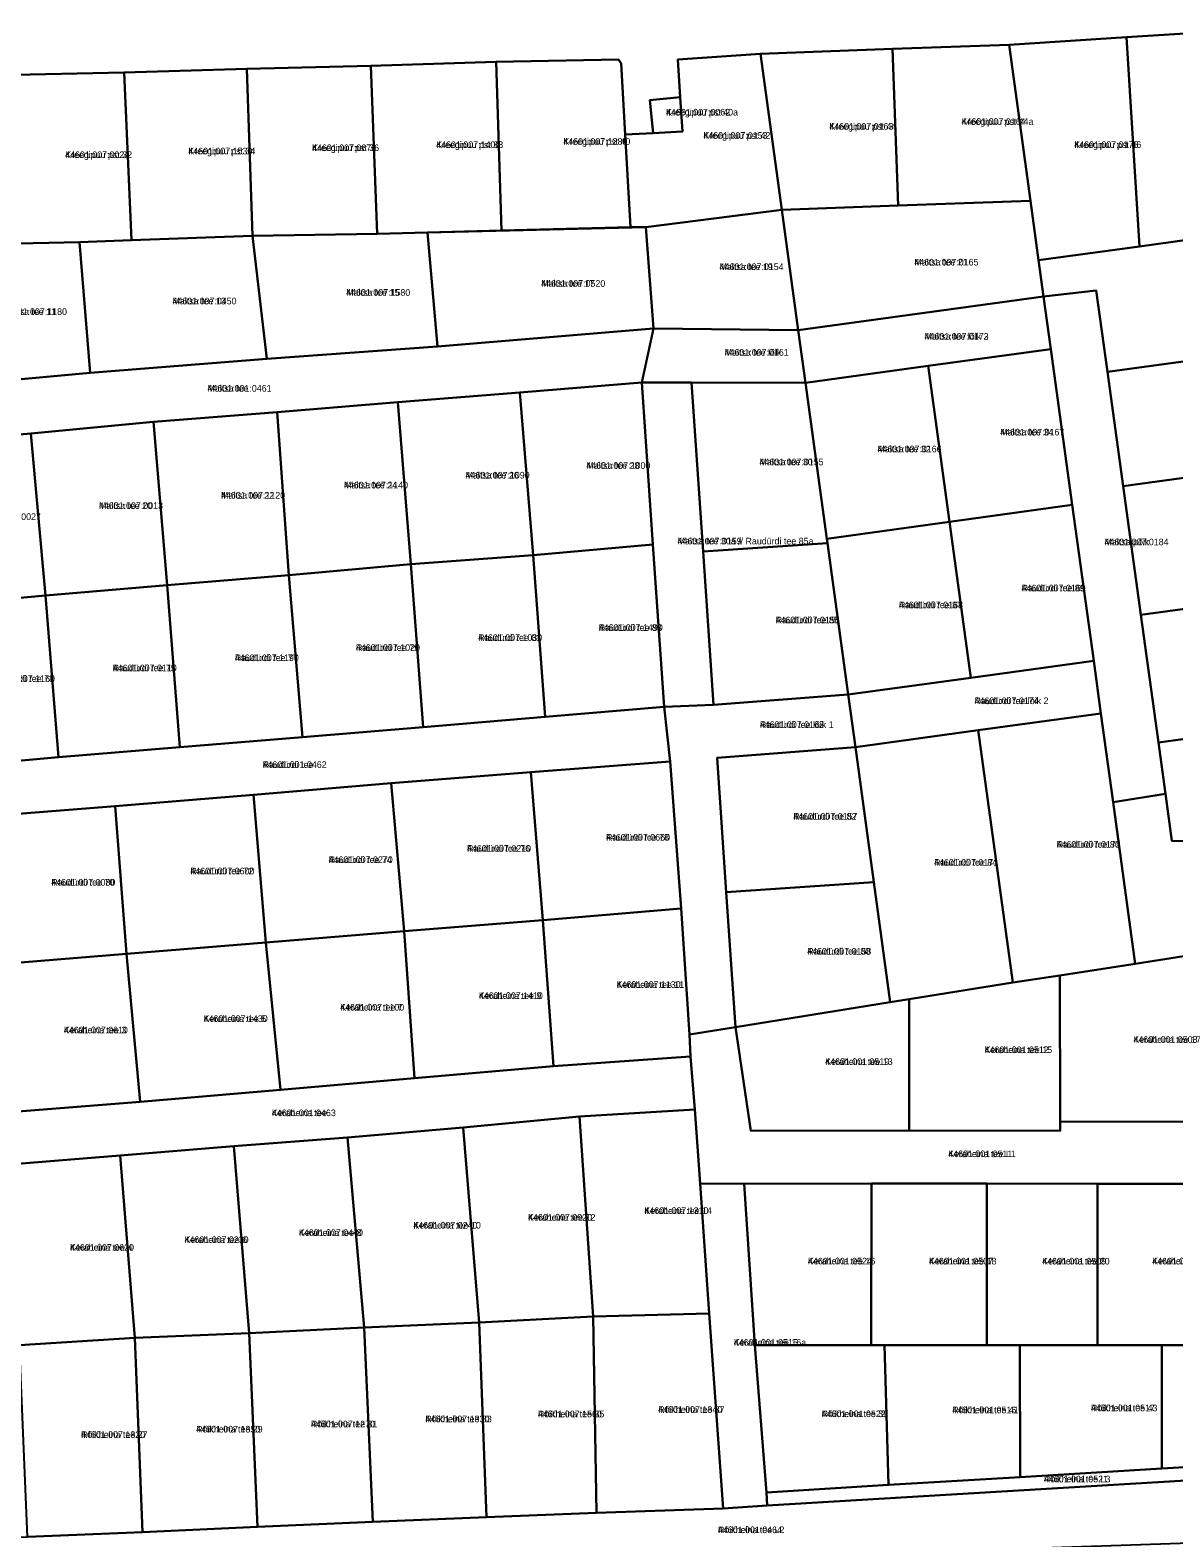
# Model space of a CAD drawing. Extents: x 551843 to 558501, y 6589003 to 6595718.
# Drawn here: x 554119.5 to 554378.5, y 6592709.8 to 6593051.3 of the extents above; entities that cross this region are included whole.
import ezdxf

# ---------------------------------------------------------------- set-up
doc = ezdxf.new("R2010")
doc.units = 0
for name, color, linetype in [('L_AADRESS', 7, 'Continuous'), ('PIIR', 7, 'Continuous'), ('TUNNUS', 7, 'Continuous')]:
    doc.layers.add(name, color=color, linetype=linetype)

msp = doc.modelspace()

# ---------------------------------------------------------------- linework, layer by layer
at = {"layer": 'PIIR'}
msp.add_lwpolyline([(554393.23, 6593051.33), (554367.77, 6593049.72), (554341.21, 6593048.04), (554314.82, 6593047.08), (554284.88, 6593045.98), (554266.15, 6593044.67), (554266.74, 6593036.15), (554259.82, 6593035.44), (554260.58, 6593028.02), (554254.24, 6593027.69), (554253.32, 6593043.75), (554252.74, 6593044.67), (554225.05, 6593044.16), (554196.68, 6593043.29), (554168.59, 6593042.59), (554140.76, 6593041.72), (554112.35, 6593041.16), (554083.78, 6593040.41), (554051.46, 6593039.45), (554047.89, 6593060.25)], dxfattribs=at)
for points in [[(554367.77, 6593049.72), (554393.23, 6593051.33), (554395.81, 6593015.41), (554397.21, 6593005.99), (554370.76, 6593002.33)], [(554314.82, 6593047.08), (554341.21, 6593048.04), (554346.06, 6593012.7), (554316.12, 6593011.6)], [(554341.21, 6593048.04), (554367.77, 6593049.72), (554370.76, 6593002.33), (554347.91, 6592999.22), (554346.06, 6593012.7)], [(554252.74, 6593044.67), (554253.32, 6593043.75), (554254.24, 6593027.69), (554255.46, 6593006.67), (554226.23, 6593005.95), (554225.05, 6593044.16)], [(554266.15, 6593044.67), (554284.88, 6593045.98), (554289.73, 6593010.63), (554258.95, 6593006.73), (554255.46, 6593006.67), (554254.24, 6593027.69), (554260.58, 6593028.02), (554267.22, 6593028.37), (554266.74, 6593036.15)], [(554284.88, 6593045.98), (554314.82, 6593047.08), (554316.12, 6593011.6), (554289.73, 6593010.63)], [(554130.68, 6593003.34), (554113.25, 6593002.9), (554112.35, 6593041.16), (554140.76, 6593041.72), (554142.47, 6593003.75)], [(554140.76, 6593041.72), (554168.59, 6593042.59), (554169.86, 6593004.71), (554142.47, 6593003.75)], [(554196.68, 6593043.29), (554198.09, 6593005.16), (554169.86, 6593004.71), (554168.59, 6593042.59)], [(554198.09, 6593005.16), (554196.68, 6593043.29), (554225.05, 6593044.16), (554226.23, 6593005.95), (554209.46, 6593005.46)], [(554266.74, 6593036.15), (554267.22, 6593028.37), (554260.58, 6593028.02), (554259.82, 6593035.44)], [(554258.95, 6593006.73), (554289.73, 6593010.63), (554293.47, 6592983.34), (554260.66, 6592983.71)], [(554289.73, 6593010.63), (554316.12, 6593011.6), (554346.06, 6593012.7), (554347.91, 6592999.22), (554349.04, 6592990.97), (554293.47, 6592983.34)], [(554142.47, 6593003.75), (554169.86, 6593004.71), (554173.07, 6592976.86), (554133.06, 6592973.7), (554130.68, 6593003.34)], [(554169.86, 6593004.71), (554198.09, 6593005.16), (554209.46, 6593005.46), (554211.72, 6592979.66), (554173.07, 6592976.86)], [(554209.46, 6593005.46), (554258.95, 6593006.73), (554260.66, 6592983.71), (554211.72, 6592979.66)], [(554347.91, 6592999.22), (554370.76, 6593002.33), (554397.21, 6593005.99), (554400.85, 6592981.48), (554401.21, 6592979.08), (554363.49, 6592973.9), (554360.96, 6592992.34), (554349.04, 6592990.97)], [(554093.35, 6593002.34), (554113.25, 6593002.9), (554130.68, 6593003.34), (554133.06, 6592973.7), (554095.98, 6592970.3)], [(554293.47, 6592983.34), (554349.04, 6592990.97), (554350.68, 6592979.08), (554322.88, 6592975.26), (554295.1, 6592971.45)], [(554349.04, 6592990.97), (554360.96, 6592992.34), (554363.49, 6592973.9), (554367.05, 6592947.99), (554371.05, 6592918.84), (554375.02, 6592889.95), (554376.62, 6592878.3), (554364.77, 6592876.42), (554362.01, 6592896.54), (554360.38, 6592908.43), (554355.53, 6592943.76), (554350.68, 6592979.08)], [(554061.41, 6592967.05), (554095.98, 6592970.3), (554133.06, 6592973.7), (554173.07, 6592976.86), (554211.72, 6592979.66), (554260.66, 6592983.71), (554258, 6592971.5), (554230.39, 6592969.26), (554202.78, 6592967.02), (554175.41, 6592964.8), (554147.41, 6592962.61), (554119.61, 6592959.98), (554091.85, 6592957.57), (554062.46, 6592955.16)], [(554260.66, 6592983.71), (554293.47, 6592983.34), (554295.1, 6592971.45), (554269.29, 6592971.48), (554258, 6592971.5)], [(554322.88, 6592975.26), (554350.68, 6592979.08), (554355.53, 6592943.76), (554327.73, 6592939.94)], [(554363.49, 6592973.9), (554401.21, 6592979.08), (554405.05, 6592953.2), (554367.05, 6592947.99)], [(554295.1, 6592971.45), (554322.88, 6592975.26), (554327.73, 6592939.94), (554299.94, 6592936.12)], [(554260.5, 6592934.8), (554233.44, 6592932.37), (554230.39, 6592969.26), (554258, 6592971.5)], [(554258, 6592971.5), (554269.29, 6592971.48), (554271.9, 6592933.21), (554274.26, 6592898.5), (554263.08, 6592898.06), (554260.5, 6592934.8)], [(554269.29, 6592971.48), (554295.1, 6592971.45), (554299.94, 6592936.12), (554300.08, 6592935.13), (554271.9, 6592933.21)], [(554205.74, 6592930.34), (554178.05, 6592927.87), (554175.41, 6592964.8), (554202.78, 6592967.02)], [(554233.44, 6592932.37), (554205.74, 6592930.34), (554202.78, 6592967.02), (554230.39, 6592969.26)], [(554122.96, 6592923.26), (554119.61, 6592959.98), (554147.41, 6592962.61), (554150.53, 6592925.62)], [(554147.41, 6592962.61), (554175.41, 6592964.8), (554178.05, 6592927.87), (554150.53, 6592925.62)], [(554119.61, 6592959.98), (554122.96, 6592923.26), (554095.24, 6592920.69), (554091.85, 6592957.57)], [(554367.05, 6592947.99), (554405.05, 6592953.2), (554407.03, 6592939.78), (554409.37, 6592924.1), (554371.05, 6592918.84)], [(554327.73, 6592939.94), (554355.53, 6592943.76), (554360.38, 6592908.43), (554332.58, 6592904.61)], [(554299.94, 6592936.12), (554327.73, 6592939.94), (554332.58, 6592904.61), (554304.78, 6592900.8), (554300.08, 6592935.13)], [(554271.9, 6592933.21), (554300.08, 6592935.13), (554304.78, 6592900.8), (554274.26, 6592898.5)], [(554233.44, 6592932.37), (554236.15, 6592895.73), (554208.49, 6592893.43), (554205.74, 6592930.34)], [(554233.44, 6592932.37), (554260.5, 6592934.8), (554263.08, 6592898.06), (554236.15, 6592895.73)], [(554178.05, 6592927.87), (554205.74, 6592930.34), (554208.49, 6592893.43), (554181.16, 6592891.18)], [(554150.53, 6592925.62), (554153.39, 6592888.86), (554125.93, 6592886.61), (554122.96, 6592923.26)], [(554150.53, 6592925.62), (554178.05, 6592927.87), (554181.16, 6592891.18), (554153.39, 6592888.86)], [(554122.96, 6592923.26), (554125.93, 6592886.61), (554098.28, 6592884.15), (554095.24, 6592920.69)], [(554371.05, 6592918.84), (554409.37, 6592924.1), (554410.22, 6592918.36), (554413.54, 6592896.01), (554413.66, 6592895.25), (554375.02, 6592889.95)], [(554304.78, 6592900.8), (554332.58, 6592904.61), (554360.38, 6592908.43), (554362.01, 6592896.54), (554334.21, 6592892.72), (554306.42, 6592888.88)], [(554072.19, 6592882.01), (554098.28, 6592884.15), (554125.93, 6592886.61), (554153.39, 6592888.86), (554181.16, 6592891.18), (554208.49, 6592893.43), (554236.15, 6592895.73), (554263.08, 6592898.06), (554264.42, 6592885.66), (554232.89, 6592883.22), (554201.27, 6592880.71), (554170.05, 6592878.08), (554138.71, 6592875.53), (554107.19, 6592873.02), (554073.79, 6592870.33)], [(554263.08, 6592898.06), (554274.26, 6592898.5), (554304.78, 6592900.8), (554306.42, 6592888.88), (554275.08, 6592886.47), (554277.16, 6592856.04), (554279.26, 6592825.48), (554268.83, 6592823.82), (554266.94, 6592852.31), (554264.42, 6592885.66)], [(554334.21, 6592892.72), (554362.01, 6592896.54), (554364.77, 6592876.42), (554369.77, 6592839.83), (554352.72, 6592837.18), (554342.04, 6592835.54)], [(554375.02, 6592889.95), (554413.66, 6592895.25), (554416.39, 6592876.86), (554416.25, 6592872.95), (554416.07, 6592866.52), (554378.07, 6592867.69), (554376.62, 6592878.3)], [(554310.61, 6592858.32), (554306.42, 6592888.88), (554334.21, 6592892.72), (554342.04, 6592835.54), (554318.6, 6592831.82), (554314.31, 6592831.13)], [(554275.08, 6592886.47), (554306.42, 6592888.88), (554310.61, 6592858.32), (554277.16, 6592856.04)], [(554264.42, 6592885.66), (554266.94, 6592852.31), (554235.58, 6592849.7), (554232.89, 6592883.22)], [(554201.27, 6592880.71), (554204.18, 6592847.18), (554172.84, 6592844.61), (554170.05, 6592878.08)], [(554201.27, 6592880.71), (554232.89, 6592883.22), (554235.58, 6592849.7), (554204.18, 6592847.18)], [(554170.05, 6592878.08), (554172.84, 6592844.61), (554141.34, 6592842.08), (554138.71, 6592875.53)], [(554364.77, 6592876.42), (554376.62, 6592878.3), (554378.07, 6592867.69), (554416.07, 6592866.52), (554415.52, 6592849.35), (554415.39, 6592846.94), (554386.06, 6592842.35), (554369.77, 6592839.83)], [(554138.71, 6592875.53), (554141.34, 6592842.08), (554109.85, 6592839.49), (554107.19, 6592873.02)], [(554277.16, 6592856.04), (554310.61, 6592858.32), (554314.31, 6592831.13), (554279.26, 6592825.48)], [(554266.94, 6592852.31), (554268.83, 6592823.82), (554269.06, 6592818.81), (554238.02, 6592816.61), (554235.58, 6592849.7)], [(554204.18, 6592847.18), (554206.55, 6592813.91), (554176.22, 6592811.29), (554172.84, 6592844.61)], [(554204.18, 6592847.18), (554235.58, 6592849.7), (554238.02, 6592816.61), (554206.55, 6592813.91)], [(554141.34, 6592842.08), (554172.84, 6592844.61), (554176.22, 6592811.29), (554144.37, 6592808.55)], [(554141.34, 6592842.08), (554144.37, 6592808.55), (554113.87, 6592806.14), (554109.85, 6592839.49)], [(554352.81, 6592804.06), (554352.72, 6592837.18), (554369.77, 6592839.83), (554386.06, 6592842.35), (554386.02, 6592804.03)], [(554318.6, 6592802.02), (554318.6, 6592831.82), (554342.04, 6592835.54), (554352.72, 6592837.18), (554352.81, 6592804.06), (554352.8, 6592801.98)], [(554282.7, 6592802), (554279.26, 6592825.48), (554314.31, 6592831.13), (554318.6, 6592831.82), (554318.6, 6592802.02)], [(554269.06, 6592818.81), (554268.83, 6592823.82), (554279.26, 6592825.48), (554282.7, 6592802), (554318.6, 6592802.02), (554352.8, 6592801.98), (554352.81, 6592804.06), (554386.02, 6592804.03), (554386.04, 6592795.97), (554386.03, 6592790), (554361.23, 6592789.98), (554336.17, 6592790.01), (554310.03, 6592790.01), (554281.23, 6592789.98), (554271.27, 6592790.01), (554270.06, 6592806.81)], [(554082.62, 6592803.68), (554113.87, 6592806.14), (554144.37, 6592808.55), (554176.22, 6592811.29), (554206.55, 6592813.91), (554238.02, 6592816.61), (554269.06, 6592818.81), (554270.06, 6592806.81), (554243.92, 6592805.23), (554217.53, 6592802.75), (554191.38, 6592800.49), (554165.59, 6592798.47), (554139.85, 6592796.36), (554113.8, 6592794.24), (554084.25, 6592791.8)], [(554273.3, 6592760.55), (554246.98, 6592759.87), (554243.92, 6592805.23), (554270.06, 6592806.81), (554271.27, 6592790.01)], [(554217.53, 6592802.75), (554221.2, 6592758.52), (554195.13, 6592757.39), (554191.38, 6592800.49)], [(554243.92, 6592805.23), (554246.98, 6592759.87), (554221.2, 6592758.52), (554217.53, 6592802.75)], [(554191.38, 6592800.49), (554195.13, 6592757.39), (554169.08, 6592756.16), (554165.59, 6592798.47)], [(554139.85, 6592796.36), (554143.21, 6592755.09), (554117.09, 6592753.44), (554113.8, 6592794.24)], [(554165.59, 6592798.47), (554169.08, 6592756.16), (554143.21, 6592755.09), (554139.85, 6592796.36)], [(554273.3, 6592760.55), (554271.27, 6592790.01), (554281.23, 6592789.98), (554283.59, 6592753.4), (554286.23, 6592720.04), (554286.44, 6592717.06), (554276.46, 6592716.41)], [(554283.59, 6592753.4), (554281.23, 6592789.98), (554310.03, 6592790.01), (554309.98, 6592753.4)], [(554309.98, 6592753.4), (554310.03, 6592790.01), (554336.17, 6592790.01), (554336.16, 6592753.39), (554312.98, 6592753.39)], [(554336.16, 6592753.39), (554336.17, 6592790.01), (554361.23, 6592789.98), (554361.26, 6592753.4), (554343.67, 6592753.38)], [(554361.26, 6592753.4), (554361.23, 6592789.98), (554386.03, 6592790), (554386.04, 6592753.39), (554375.81, 6592753.4)], [(554195.13, 6592757.39), (554221.2, 6592758.52), (554222.84, 6592714.47), (554197.07, 6592713.42)], [(554221.2, 6592758.52), (554246.98, 6592759.87), (554247.74, 6592715.45), (554222.84, 6592714.47)], [(554246.98, 6592759.87), (554273.3, 6592760.55), (554276.46, 6592716.41), (554247.74, 6592715.45)], [(554143.21, 6592755.09), (554144.94, 6592711.06), (554118.91, 6592710.02), (554117.09, 6592753.44)], [(554143.21, 6592755.09), (554169.08, 6592756.16), (554170.97, 6592712.22), (554144.94, 6592711.06)], [(554169.08, 6592756.16), (554195.13, 6592757.39), (554197.07, 6592713.42), (554170.97, 6592712.22)], [(554286.23, 6592720.04), (554283.59, 6592753.4), (554309.98, 6592753.4), (554312.98, 6592753.39), (554313.92, 6592721.75)], [(554313.92, 6592721.75), (554312.98, 6592753.39), (554336.16, 6592753.39), (554343.67, 6592753.38), (554343.7, 6592723.47)], [(554343.7, 6592723.47), (554343.67, 6592753.38), (554361.26, 6592753.4), (554375.81, 6592753.4), (554375.79, 6592725.47)], [(554375.79, 6592725.47), (554375.81, 6592753.4), (554386.04, 6592753.39), (554412.52, 6592753.39), (554411.77, 6592727.61)], [(554286.44, 6592717.06), (554286.23, 6592720.04), (554313.92, 6592721.75), (554343.7, 6592723.47), (554375.79, 6592725.47), (554411.77, 6592727.61), (554411.66, 6592724.59)], [(554096.53, 6592697.08), (554093.97, 6592709.01), (554118.91, 6592710.02), (554144.94, 6592711.06), (554170.97, 6592712.22), (554197.07, 6592713.42), (554222.84, 6592714.47), (554247.74, 6592715.45), (554276.46, 6592716.41), (554286.44, 6592717.06), (554411.66, 6592724.59), (554411.2, 6592709.5), (554277.28, 6592705.03), (554247.08, 6592703.49), (554216.6, 6592702.26), (554186.13, 6592700.61), (554137.12, 6592698.41)]]:
    msp.add_lwpolyline(points, close=True, dxfattribs=at)

# ---------------------------------------------------------------- texts
at = {"layer": 'L_AADRESS'}
for s, p in [('Kreegipuu pst 40a', (554263.52, 6593032)), ('Kreegipuu pst 44a', (554330.44, 6593029.89)), ('Kreegipuu pst 42', (554271.98, 6593026.73)), ('Kreegipuu pst 44', (554300.5, 6593028.79)), ('Kreegipuu pst 32', (554127.41, 6593022.36)), ('Kreegipuu pst 34', (554155.31, 6593023.19)), ('Kreegipuu pst 36', (554183.34, 6593023.94)), ('Kreegipuu pst 38', (554211.45, 6593024.63)), ('Kreegipuu pst 40', (554240.25, 6593025.37)), ('Kreegipuu pst 46', (554355.98, 6593024.65)), ('Maltsa tee 19', (554275.64, 6592996.99)), ('Maltsa tee 21', (554319.77, 6592998.02)), ('Maltsa tee 17', (554235.24, 6592993.2)), ('Maltsa tee 13', (554151.73, 6592989.21)), ('Maltsa tee 15', (554191.07, 6592991.16)), ('Maltsa tee 11', (554113.32, 6592986.82)), ('Maltsa tee lõik 2', (554322.07, 6592981.21)), ('Maltsa tee lõik 1', (554276.79, 6592977.58)), ('Maltsa tee', (554159.66, 6592969.44)), ('Maltsa tee 34', (554339.21, 6592959.51)), ('Maltsa tee 32', (554311.41, 6592955.69)), ('Maltsa tee 28', (554245.45, 6592951.96)), ('Maltsa tee 30', (554284.68, 6592952.77)), ('Maltsa tee 24', (554190.57, 6592947.51)), ('Maltsa tee 26', (554218.11, 6592949.76)), ('Maltsa tee 22', (554162.73, 6592945.21)), ('Maltsa tee 20', (554135.07, 6592942.87)), ('Maltsa tee 30a // Raudürdi tee 85a', (554266.13, 6592934.83)), ('Maltsa põik', (554362.83, 6592934.64)), ('Raudürdi tee 89', (554344.05, 6592924.19)), ('Raudürdi tee 87', (554316.26, 6592920.37)), ('Raudürdi tee 85', (554288.34, 6592916.95)), ('Raudürdi tee 83', (554248.26, 6592915.24)), ('Raudürdi tee 79', (554193.27, 6592910.7)), ('Raudürdi tee 81', (554220.95, 6592912.96)), ('Raudürdi tee 77', (554165.84, 6592908.39)), ('Raudürdi tee 73', (554110.59, 6592903.68)), ('Raudürdi tee 75', (554138.18, 6592906.09)), ('Raudürdi tee lõik 2', (554333.4, 6592898.65)), ('Raudürdi tee lõik 1', (554284.75, 6592893.25)), ('Raudürdi tee', (554172.14, 6592884.19)), ('Raudürdi tee 82', (554292.35, 6592872.46)), ('Raudürdi tee 78', (554249.91, 6592867.72)), ('Raudürdi tee 86', (554351.99, 6592866.12)), ('Raudürdi tee 74', (554187.11, 6592862.65)), ('Raudürdi tee 76', (554218.43, 6592865.2)), ('Raudürdi tee 84', (554324.23, 6592862.03)), ('Raudürdi tee 72', (554155.78, 6592860.08)), ('Raudürdi tee 70', (554124.27, 6592857.53)), ('Raudürdi tee 80', (554295.49, 6592841.9)), ('Keraheina tee 9', (554221.1, 6592831.85)), ('Keraheina tee 11', (554252.32, 6592834.36)), ('Keraheina tee 7', (554189.7, 6592829.22)), ('Keraheina tee 5', (554158.78, 6592826.64)), ('Keraheina tee 3', (554127.11, 6592824.05)), ('Keraheina tee 17', (554369.39, 6592821.91)), ('Keraheina tee 15', (554335.68, 6592819.58)), ('Keraheina tee 13', (554299.56, 6592816.91)), ('Keraheina tee', (554174.21, 6592805.3)), ('Keraheina tee L1', (554327.43, 6592796.01)), ('Keraheina tee 10', (554206.29, 6592779.83)), ('Keraheina tee 12', (554232.25, 6592781.62)), ('Keraheina tee 14', (554258.61, 6592783.14)), ('Keraheina tee 6', (554154.46, 6592776.56)), ('Keraheina tee 8', (554180.36, 6592778.16)), ('Keraheina tee 4', (554128.5, 6592774.8)), ('Keraheina tee 16', (554295.63, 6592771.7)), ('Keraheina tee 18', (554323.07, 6592771.7)), ('Keraheina tee 20', (554348.71, 6592771.69)), ('Keraheina tee 22', (554373.63, 6592771.7)), ('Keraheina tee 16a', (554278.86, 6592753.28)), ('Rõikheina tee 33', (554208.99, 6592735.95)), ('Rõikheina tee 35', (554234.47, 6592737.07)), ('Rõikheina tee 37', (554261.72, 6592738.08)), ('Rõikheina tee 39', (554298.76, 6592737.11)), ('Rõikheina tee 41', (554328.34, 6592737.99)), ('Rõikheina tee 43', (554359.74, 6592738.43)), ('Rõikheina tee 27', (554131.02, 6592732.41)), ('Rõikheina tee 29', (554157.09, 6592733.63)), ('Rõikheina tee 31', (554183.07, 6592734.8)), ('Rõikheina tee L3', (554349.1, 6592722.33)), ('Rõikheina tee L2', (554275.27, 6592710.83))]:
    msp.add_text(s, height=1.5, dxfattribs=at).set_placement(p)
at = {"layer": 'TUNNUS'}
for s, p in [('44601:007:0062', (554263.52, 6593032)), ('44601:007:0164', (554330.44, 6593029.89)), ('44601:007:0153', (554271.98, 6593026.73)), ('44601:007:0163', (554300.5, 6593028.79)), ('44601:007:1530', (554155.31, 6593023.19)), ('44601:007:0670', (554183.34, 6593023.94)), ('44601:007:1400', (554211.45, 6593024.63)), ('44601:007:1380', (554240.25, 6593025.37)), ('44601:007:0175', (554355.98, 6593024.65)), ('44601:007:0024', (554127.41, 6593022.36)), ('44601:007:0154', (554275.64, 6592996.99)), ('44601:007:0165', (554319.77, 6592998.02)), ('44601:007:0520', (554235.24, 6592993.2)), ('44601:007:0450', (554151.73, 6592989.21)), ('44601:007:1580', (554191.07, 6592991.16)), ('44601:007:1180', (554113.32, 6592986.82)), ('44601:007:0173', (554322.07, 6592981.21)), ('44601:007:0161', (554276.79, 6592977.58)), ('44601:001:0461', (554159.66, 6592969.44)), ('44601:007:0167', (554339.21, 6592959.51)), ('44601:007:0166', (554311.41, 6592955.69)), ('44601:007:1000', (554245.45, 6592951.96)), ('44601:007:0155', (554284.68, 6592952.77)), ('44601:007:1140', (554190.57, 6592947.51)), ('44601:007:1090', (554218.11, 6592949.76)), ('44601:007:1120', (554162.73, 6592945.21)), ('44601:007:0013', (554135.07, 6592942.87)), ('44601:007:0027', (554107.41, 6592940.37)), ('44601:007:0159', (554266.13, 6592934.83)), ('44601:007:0184', (554362.83, 6592934.64)), ('44601:007:0169', (554344.05, 6592924.19)), ('44601:007:0168', (554316.26, 6592920.37)), ('44601:007:0156', (554288.34, 6592916.95)), ('44601:007:1490', (554248.26, 6592915.24)), ('44601:007:1020', (554193.27, 6592910.7)), ('44601:007:1030', (554220.95, 6592912.96)), ('44601:007:1190', (554165.84, 6592908.39)), ('44601:007:1160', (554110.59, 6592903.68)), ('44601:007:0110', (554138.18, 6592906.09)), ('44601:007:0174', (554333.4, 6592898.65)), ('44601:007:0162', (554284.75, 6592893.25)), ('44601:001:0462', (554172.14, 6592884.19)), ('44601:007:0157', (554292.35, 6592872.46)), ('44601:007:0660', (554249.91, 6592867.72)), ('44601:007:0172', (554351.99, 6592866.12)), ('44601:007:0270', (554187.11, 6592862.65)), ('44601:007:0210', (554218.43, 6592865.2)), ('44601:007:0171', (554324.23, 6592862.03)), ('44601:007:0600', (554155.78, 6592860.08)), ('44601:007:0080', (554124.27, 6592857.53)), ('44601:007:0158', (554295.49, 6592841.9)), ('44601:007:1410', (554221.1, 6592831.85)), ('44601:007:1130', (554252.32, 6592834.36)), ('44601:007:1100', (554189.7, 6592829.22)), ('44601:007:1430', (554158.78, 6592826.64)), ('44601:007:0610', (554127.11, 6592824.05)), ('44601:001:0508', (554369.39, 6592821.91)), ('44601:001:0512', (554335.68, 6592819.58)), ('44601:001:0519', (554299.56, 6592816.91)), ('44601:001:0463', (554174.21, 6592805.3)), ('44601:001:0511', (554327.43, 6592796.01)), ('44601:007:0920', (554232.25, 6592781.62)), ('44601:007:1310', (554258.61, 6592783.14)), ('44601:007:0230', (554154.46, 6592776.56)), ('44601:007:0440', (554180.36, 6592778.16)), ('44601:007:0240', (554206.29, 6592779.83)), ('44601:007:0620', (554128.5, 6592774.8)), ('44601:001:0524', (554295.63, 6592771.7)), ('44601:001:0507', (554323.07, 6592771.7)), ('44601:001:0509', (554348.71, 6592771.69)), ('44601:001:0513', (554373.63, 6592771.7)), ('44601:001:0515', (554278.86, 6592753.28)), ('44601:007:1330', (554208.99, 6592735.95)), ('44601:007:1560', (554234.47, 6592737.07)), ('44601:007:1340', (554261.72, 6592738.08)), ('44601:001:0522', (554298.76, 6592737.11)), ('44601:001:0516', (554328.34, 6592737.99)), ('44601:001:0517', (554359.74, 6592738.43)), ('44601:007:1320', (554131.02, 6592732.41)), ('44601:007:1350', (554157.09, 6592733.63)), ('44601:007:1270', (554183.07, 6592734.8)), ('44601:001:0521', (554349.1, 6592722.33)), ('44601:001:0464', (554275.27, 6592710.83))]:
    msp.add_text(s, height=1.5, dxfattribs=at).set_placement(p)

doc.saveas('drawing.dxf')
